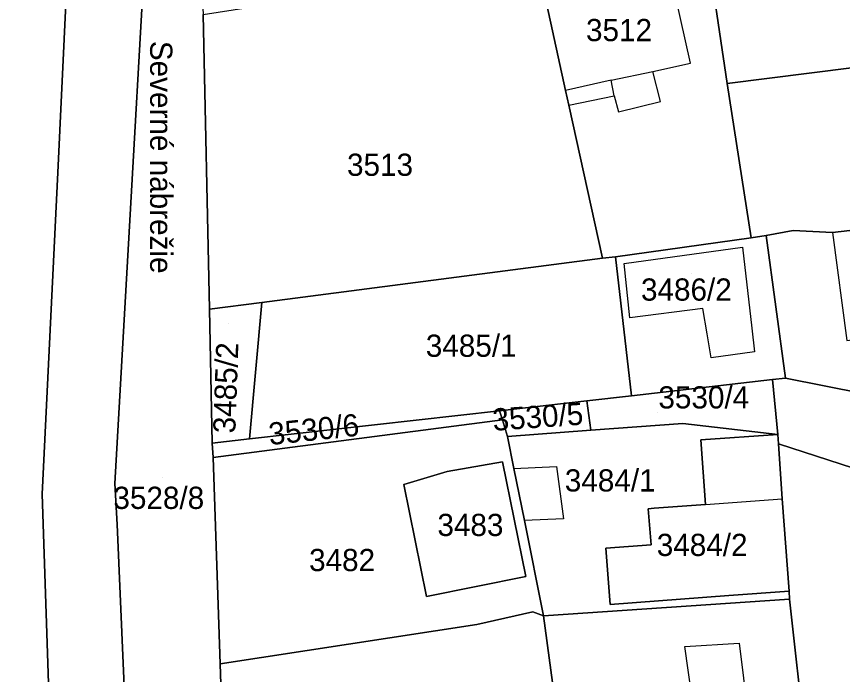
# Model space of a CAD drawing. Extents: x -262657 to -261595, y -1238015 to -1237156.
# Drawn here: x -262343.6 to -262269.2, y -1237502.5 to -1237443.2 of the extents above; entities that cross this region are included whole.
import ezdxf

# ---------------------------------------------------------------- set-up
doc = ezdxf.new("R2010")
doc.units = 0
for name, color, linetype in [('body_kn', 7, 'Continuous'), ('kladpar_druhypozemkov', 7, 'Continuous'), ('kladpar_hranice', 7, 'Continuous'), ('kladpar_parcelnecisla', 7, 'Continuous'), ('kladpar_plochy', 7, 'Continuous'), ('popisy', 7, 'Continuous'), ('zappar_hrandruhpozemk', 7, 'Continuous')]:
    doc.layers.add(name, color=color, linetype=linetype)

msp = doc.modelspace()

# ---------------------------------------------------------------- linework, layer by layer
at = {"layer": 'body_kn'}
for p, q in [((-262282.91, -1237447.41), (-262282.91, -1237447.41)), ((-262286.31, -1237448.15), (-262286.31, -1237448.15)), ((-262290.07, -1237448.94), (-262290.07, -1237448.94)), ((-262279.63, -1237449.24), (-262279.63, -1237449.24)), ((-262279.63, -1237449.24), (-262279.63, -1237449.24)), ((-262294.17, -1237449.87), (-262294.17, -1237449.87)), ((-262289.79, -1237450.34), (-262289.79, -1237450.34)), ((-262289.79, -1237450.34), (-262289.79, -1237450.34)), ((-262285.61, -1237450.85), (-262285.61, -1237450.85)), ((-262293.89, -1237451.17), (-262293.89, -1237451.17)), ((-262293.89, -1237451.17), (-262293.89, -1237451.17)), ((-262289.4, -1237451.78), (-262289.4, -1237451.78)), ((-262339.94, -1237457.24), (-262339.94, -1237457.24)), ((-262276.1, -1237462.91), (-262276.1, -1237462.91)), ((-262273.67, -1237462.47), (-262273.67, -1237462.47)), ((-262270.12, -1237462.65), (-262270.12, -1237462.65)), ((-262270.12, -1237462.65), (-262270.12, -1237462.65)), ((-262333.57, -1237463.66), (-262333.57, -1237463.66)), ((-262277.44, -1237463.14), (-262277.44, -1237463.14)), ((-262277.44, -1237463.14), (-262277.44, -1237463.14)), ((-262278.22, -1237463.98), (-262278.22, -1237463.98)), ((-262278.22, -1237463.98), (-262278.22, -1237463.98)), ((-262290.86, -1237464.97), (-262290.86, -1237464.97)), ((-262289.69, -1237464.84), (-262289.69, -1237464.84)), ((-262289.69, -1237464.84), (-262289.69, -1237464.84)), ((-262288.91, -1237465.43), (-262288.91, -1237465.43)), ((-262326.27, -1237469.57), (-262326.27, -1237469.57)), ((-262326.27, -1237469.57), (-262326.27, -1237469.57)), ((-262321.56, -1237468.96), (-262321.56, -1237468.96)), ((-262281.81, -1237469.51), (-262281.81, -1237469.51)), ((-262288.39, -1237470.34), (-262288.39, -1237470.34)), ((-262281.43, -1237471.79), (-262281.43, -1237471.79)), ((-262277.39, -1237471.27), (-262277.39, -1237471.27)), ((-262277.15, -1237473.39), (-262277.15, -1237473.39)), ((-262281.07, -1237473.95), (-262281.07, -1237473.95)), ((-262275.54, -1237475.9), (-262275.54, -1237475.9)), ((-262275.54, -1237475.9), (-262275.54, -1237475.9)), ((-262274.37, -1237475.76), (-262274.37, -1237475.76)), ((-262292.26, -1237477.81), (-262292.26, -1237477.81)), ((-262292.26, -1237477.81), (-262292.26, -1237477.81)), ((-262288.23, -1237477.35), (-262288.23, -1237477.35)), ((-262300.12, -1237478.7), (-262300.12, -1237478.7)), ((-262300.12, -1237478.7), (-262300.12, -1237478.7)), ((-262299.89, -1237478.67), (-262299.89, -1237478.67)), ((-262299.87, -1237479.53), (-262299.87, -1237479.53)), ((-262283.62, -1237479.85), (-262283.62, -1237479.85)), ((-262283.62, -1237479.85), (-262283.62, -1237479.85)), ((-262291.89, -1237480.47), (-262291.89, -1237480.47)), ((-262275.05, -1237480.84), (-262275.05, -1237480.84)), ((-262322.67, -1237481.24), (-262322.67, -1237481.24)), ((-262299.42, -1237481.04), (-262299.42, -1237481.04)), ((-262281.98, -1237481.33), (-262281.98, -1237481.33)), ((-262326.03, -1237481.62), (-262326.03, -1237481.62)), ((-262326.03, -1237481.62), (-262326.03, -1237481.62)), ((-262275, -1237481.7), (-262275, -1237481.7)), ((-262275, -1237481.7), (-262275, -1237481.7)), ((-262325.93, -1237482.92), (-262325.93, -1237482.92)), ((-262299.85, -1237483.3), (-262299.85, -1237483.3)), ((-262295, -1237483.73), (-262295, -1237483.73)), ((-262304.85, -1237484.19), (-262304.85, -1237484.19)), ((-262298.83, -1237483.91), (-262298.83, -1237483.91)), ((-262298.83, -1237483.91), (-262298.83, -1237483.91)), ((-262334.8, -1237485.25), (-262334.8, -1237485.25)), ((-262308.74, -1237485.35), (-262308.74, -1237485.35)), ((-262341.34, -1237486.23), (-262341.34, -1237486.23)), ((-262274.65, -1237486.63), (-262274.65, -1237486.63)), ((-262286.72, -1237487.53), (-262286.72, -1237487.53)), ((-262286.18, -1237487.49), (-262286.18, -1237487.49)), ((-262281.57, -1237487.15), (-262281.57, -1237487.15)), ((-262281.57, -1237487.15), (-262281.57, -1237487.15)), ((-262334.58, -1237488.96), (-262334.58, -1237488.96)), ((-262297.89, -1237488.59), (-262297.89, -1237488.59)), ((-262294.36, -1237488.44), (-262294.36, -1237488.44)), ((-262290.56, -1237491.08), (-262290.56, -1237491.08)), ((-262286.47, -1237490.77), (-262286.47, -1237490.77)), ((-262297.76, -1237493.64), (-262297.76, -1237493.64)), ((-262274.04, -1237494.95), (-262274.04, -1237494.95)), ((-262306.7, -1237495.45), (-262306.7, -1237495.45)), ((-262306.7, -1237495.45), (-262306.7, -1237495.45)), ((-262279.47, -1237495.36), (-262279.47, -1237495.36)), ((-262274, -1237495.67), (-262274, -1237495.67)), ((-262274, -1237495.67), (-262274, -1237495.67)), ((-262290.17, -1237496.17), (-262290.17, -1237496.17)), ((-262297.12, -1237496.83), (-262297.12, -1237496.83)), ((-262296.18, -1237497.18), (-262296.18, -1237497.18)), ((-262302.16, -1237497.96), (-262302.16, -1237497.96)), ((-262302.16, -1237497.96), (-262302.16, -1237497.96)), ((-262283.44, -1237499.94), (-262283.44, -1237499.94)), ((-262278.53, -1237499.64), (-262278.53, -1237499.64)), ((-262325.3, -1237501.49), (-262325.3, -1237501.49)), ((-262325.3, -1237501.49), (-262325.3, -1237501.49))]:
    msp.add_line(p, q, dxfattribs=at)
at = {"layer": 'kladpar_druhypozemkov'}
for p, q in [((-262311.05, -1237455.55), (-262311.05, -1237455.55)), ((-262282.84, -1237466.33), (-262282.84, -1237466.33)), ((-262324.59, -1237470.81), (-262324.59, -1237470.81)), ((-262301.97, -1237471.82), (-262301.97, -1237471.82)), ((-262294.83, -1237479.08), (-262294.83, -1237479.08)), ((-262285.85, -1237478.9), (-262285.85, -1237478.9)), ((-262310.39, -1237480.63), (-262310.39, -1237480.63)), ((-262330.51, -1237484.71), (-262330.51, -1237484.71)), ((-262289.93, -1237484.63), (-262289.93, -1237484.63)), ((-262302.46, -1237487.87), (-262302.46, -1237487.87)), ((-262280.41, -1237489.91), (-262280.41, -1237489.91)), ((-262313.9, -1237491.54), (-262313.9, -1237491.54))]:
    msp.add_line(p, q, dxfattribs=at)
at = {"layer": 'kladpar_hranice'}
for points in [[(-262343.65, -1237365.15), (-262343.6, -1237424.44), (-262343.15, -1237429.64), (-262338.68, -1237430.7), (-262338.79, -1237433.17), (-262339.94, -1237457.24), (-262341.34, -1237486.23), (-262339.66, -1237536.38)], [(-262326.86, -1237377.31), (-262329, -1237395.2), (-262330, -1237408.65), (-262330.77, -1237419.19), (-262331.73, -1237432.47), (-262332.03, -1237436.68), (-262333.57, -1237463.66), (-262334.8, -1237485.25), (-262334.58, -1237488.96), (-262332.58, -1237535.43), (-262332.11, -1237546.54), (-262332.06, -1237547.64), (-262339.28, -1237547.74), (-262339.33, -1237546.39), (-262339.66, -1237536.38), (-262341.34, -1237486.23), (-262339.94, -1237457.24), (-262338.79, -1237433.17), (-262338.68, -1237430.7), (-262338.44, -1237425.28), (-262337.84, -1237412.47), (-262336.73, -1237391.76)], [(-262281.57, -1237436.05), (-262262.7, -1237431.53), (-262261.1, -1237437.34), (-262258.95, -1237436.83), (-262257.9, -1237436.55), (-262256.26, -1237443.07), (-262235.03, -1237440.39), (-262237.65, -1237443.96), (-262256.96, -1237446.38), (-262279.63, -1237449.24), (-262281.57, -1237436.05)], [(-262331.73, -1237432.47), (-262327.33, -1237433.68), (-262326.82, -1237443.01), (-262326.27, -1237469.57), (-262326.03, -1237481.62), (-262325.93, -1237482.92), (-262325.3, -1237501.49), (-262324.89, -1237514.36), (-262325.13, -1237524.79), (-262325.13, -1237534.95), (-262332.58, -1237535.43), (-262334.58, -1237488.96), (-262334.8, -1237485.25), (-262333.57, -1237463.66), (-262332.03, -1237436.68), (-262331.73, -1237432.47)], [(-262289.69, -1237464.84), (-262290.86, -1237464.97), (-262293.89, -1237451.17), (-262294.17, -1237449.87), (-262296.39, -1237439.77), (-262296.71, -1237438.31), (-262291.42, -1237437.45), (-262281.57, -1237436.05), (-262279.63, -1237449.24), (-262277.44, -1237463.14), (-262289.69, -1237464.84)], [(-262326.27, -1237469.57), (-262326.82, -1237443.01), (-262296.71, -1237438.31), (-262296.39, -1237439.77), (-262294.17, -1237449.87), (-262293.89, -1237451.17), (-262290.86, -1237464.97), (-262321.56, -1237468.96), (-262326.27, -1237469.57)], [(-262279.63, -1237449.24), (-262256.96, -1237446.38), (-262237.65, -1237443.96), (-262237.36, -1237447.78), (-262242.94, -1237448.59), (-262242.2, -1237458.94), (-262254.6, -1237460.42), (-262255.2, -1237460.55), (-262259.69, -1237461.46), (-262270.12, -1237462.65), (-262273.67, -1237462.47), (-262276.1, -1237462.91), (-262277.44, -1237463.14), (-262279.63, -1237449.24)], [(-262249.82, -1237480.64), (-262274.37, -1237475.76), (-262276.1, -1237462.91), (-262273.67, -1237462.47), (-262270.12, -1237462.65), (-262259.69, -1237461.46), (-262255.2, -1237460.55), (-262254.6, -1237460.42), (-262251.24, -1237474.01), (-262249.82, -1237480.64)], [(-262277.44, -1237463.14), (-262276.1, -1237462.91), (-262274.37, -1237475.76), (-262275.54, -1237475.9), (-262288.23, -1237477.35), (-262289.69, -1237464.84), (-262277.44, -1237463.14)], [(-262289.69, -1237464.84), (-262288.23, -1237477.35), (-262292.26, -1237477.81), (-262299.89, -1237478.67), (-262300.12, -1237478.7), (-262322.67, -1237481.24), (-262321.56, -1237468.96), (-262290.86, -1237464.97), (-262289.69, -1237464.84)], [(-262326.03, -1237481.62), (-262326.27, -1237469.57), (-262321.56, -1237468.96), (-262322.67, -1237481.24), (-262326.03, -1237481.62)], [(-262275.54, -1237475.9), (-262275.05, -1237480.84), (-262283.62, -1237479.85), (-262291.89, -1237480.47), (-262292.26, -1237477.81), (-262288.23, -1237477.35), (-262275.54, -1237475.9)], [(-262253.7, -1237488.58), (-262275, -1237481.7), (-262275.05, -1237480.84), (-262275.54, -1237475.9), (-262274.37, -1237475.76), (-262249.82, -1237480.64)], [(-262292.26, -1237477.81), (-262291.89, -1237480.47), (-262299.42, -1237481.04), (-262299.87, -1237479.53), (-262300.12, -1237478.7), (-262299.89, -1237478.67), (-262292.26, -1237477.81)], [(-262300.12, -1237478.7), (-262299.87, -1237479.53), (-262325.93, -1237482.92), (-262326.03, -1237481.62), (-262322.67, -1237481.24), (-262300.12, -1237478.7)], [(-262325.3, -1237501.49), (-262325.93, -1237482.92), (-262299.87, -1237479.53), (-262299.42, -1237481.04), (-262298.83, -1237483.91), (-262297.89, -1237488.59), (-262296.18, -1237497.18)], [(-262283.62, -1237479.85), (-262275.05, -1237480.84), (-262281.98, -1237481.33), (-262281.57, -1237487.15), (-262286.18, -1237487.49), (-262286.72, -1237487.53), (-262286.47, -1237490.77), (-262290.56, -1237491.08), (-262290.17, -1237496.17), (-262279.47, -1237495.36), (-262274.04, -1237494.95), (-262274, -1237495.67), (-262296.18, -1237497.18), (-262297.89, -1237488.59), (-262298.83, -1237483.91), (-262299.42, -1237481.04), (-262291.89, -1237480.47), (-262283.62, -1237479.85)], [(-262281.57, -1237487.15), (-262281.98, -1237481.33), (-262275.05, -1237480.84), (-262275, -1237481.7), (-262274.65, -1237486.63), (-262274.04, -1237494.95), (-262279.47, -1237495.36), (-262290.17, -1237496.17), (-262290.56, -1237491.08), (-262286.47, -1237490.77), (-262286.72, -1237487.53), (-262286.18, -1237487.49), (-262281.57, -1237487.15)], [(-262275, -1237481.7), (-262253.7, -1237488.58), (-262252.4, -1237496.67), (-262250.53, -1237510.33), (-262257.99, -1237511.25), (-262257.63, -1237514.11), (-262271.94, -1237516.16), (-262272.6, -1237508.36), (-262274, -1237495.67), (-262274.04, -1237494.95), (-262274.65, -1237486.63), (-262275, -1237481.7)], [(-262297.76, -1237493.64), (-262299.85, -1237483.3), (-262304.85, -1237484.19), (-262308.74, -1237485.35), (-262306.7, -1237495.45), (-262297.76, -1237493.64)], [(-262306.7, -1237495.45), (-262308.74, -1237485.35), (-262304.85, -1237484.19), (-262299.85, -1237483.3), (-262297.76, -1237493.64), (-262306.7, -1237495.45)], [(-262274, -1237495.67), (-262272.6, -1237508.36), (-262273.09, -1237508.39), (-262277.39, -1237508.85), (-262282.06, -1237509.39), (-262284.85, -1237509.74), (-262294.34, -1237510.76), (-262296.18, -1237497.18), (-262274, -1237495.67)], [(-262296.18, -1237497.18), (-262297.12, -1237496.83), (-262302.16, -1237497.96), (-262325.3, -1237501.49)], [(-262302.16, -1237497.96), (-262297.12, -1237496.83), (-262296.18, -1237497.18), (-262294.34, -1237510.76), (-262310.72, -1237512.59), (-262317.09, -1237513.38), (-262324.89, -1237514.36), (-262325.3, -1237501.49), (-262302.16, -1237497.96)]]:
    msp.add_lwpolyline(points, dxfattribs=at)
at = {"layer": 'kladpar_plochy'}
for p, q in [((-262325.93, -1237482.92), (-262299.87, -1237479.53)), ((-262299.87, -1237479.53), (-262299.42, -1237481.04)), ((-262299.42, -1237481.04), (-262298.83, -1237483.91)), ((-262325.3, -1237501.49), (-262325.93, -1237482.92)), ((-262299.85, -1237483.3), (-262304.85, -1237484.19)), ((-262297.76, -1237493.64), (-262299.85, -1237483.3)), ((-262304.85, -1237484.19), (-262308.74, -1237485.35)), ((-262298.83, -1237483.91), (-262297.89, -1237488.59)), ((-262308.74, -1237485.35), (-262306.7, -1237495.45)), ((-262297.89, -1237488.59), (-262296.18, -1237497.18)), ((-262306.7, -1237495.45), (-262297.76, -1237493.64)), ((-262297.12, -1237496.83), (-262302.16, -1237497.96)), ((-262296.18, -1237497.18), (-262297.12, -1237496.83)), ((-262302.16, -1237497.96), (-262325.3, -1237501.49))]:
    msp.add_line(p, q, dxfattribs=at)
for points in [[(-262343.65, -1237365.15), (-262343.6, -1237424.44), (-262343.15, -1237429.64), (-262338.68, -1237430.7), (-262338.79, -1237433.17), (-262339.94, -1237457.24), (-262341.34, -1237486.23), (-262339.66, -1237536.38)], [(-262326.86, -1237377.31), (-262329, -1237395.2), (-262330, -1237408.65), (-262330.77, -1237419.19), (-262331.73, -1237432.47), (-262332.03, -1237436.68), (-262333.57, -1237463.66), (-262334.8, -1237485.25), (-262334.58, -1237488.96), (-262332.58, -1237535.43), (-262332.11, -1237546.54), (-262332.06, -1237547.64), (-262339.28, -1237547.74), (-262339.33, -1237546.39), (-262339.66, -1237536.38), (-262341.34, -1237486.23), (-262339.94, -1237457.24), (-262338.79, -1237433.17), (-262338.68, -1237430.7), (-262338.44, -1237425.28), (-262337.84, -1237412.47), (-262336.73, -1237391.76)], [(-262253.7, -1237488.58), (-262275, -1237481.7), (-262275.05, -1237480.84), (-262275.54, -1237475.9), (-262274.37, -1237475.76), (-262249.82, -1237480.64)]]:
    msp.add_lwpolyline(points, dxfattribs=at)
for points in [[(-262281.57, -1237436.05), (-262262.7, -1237431.53), (-262261.1, -1237437.34), (-262258.95, -1237436.83), (-262257.9, -1237436.55), (-262256.26, -1237443.07), (-262235.03, -1237440.39), (-262237.65, -1237443.96), (-262256.96, -1237446.38), (-262279.63, -1237449.24)], [(-262331.73, -1237432.47), (-262327.33, -1237433.68), (-262326.82, -1237443.01), (-262326.27, -1237469.57), (-262326.03, -1237481.62), (-262325.93, -1237482.92), (-262325.3, -1237501.49), (-262324.89, -1237514.36), (-262325.13, -1237524.79), (-262325.13, -1237534.95), (-262332.58, -1237535.43), (-262334.58, -1237488.96), (-262334.8, -1237485.25), (-262333.57, -1237463.66), (-262332.03, -1237436.68)], [(-262289.69, -1237464.84), (-262290.86, -1237464.97), (-262293.89, -1237451.17), (-262294.17, -1237449.87), (-262296.39, -1237439.77), (-262296.71, -1237438.31), (-262291.42, -1237437.45), (-262281.57, -1237436.05), (-262279.63, -1237449.24), (-262277.44, -1237463.14)], [(-262326.27, -1237469.57), (-262326.82, -1237443.01), (-262296.71, -1237438.31), (-262296.39, -1237439.77), (-262294.17, -1237449.87), (-262293.89, -1237451.17), (-262290.86, -1237464.97), (-262321.56, -1237468.96)], [(-262279.63, -1237449.24), (-262256.96, -1237446.38), (-262237.65, -1237443.96), (-262237.36, -1237447.78), (-262242.94, -1237448.59), (-262242.2, -1237458.94), (-262254.6, -1237460.42), (-262255.2, -1237460.55), (-262259.69, -1237461.46), (-262270.12, -1237462.65), (-262273.67, -1237462.47), (-262276.1, -1237462.91), (-262277.44, -1237463.14)], [(-262249.82, -1237480.64), (-262274.37, -1237475.76), (-262276.1, -1237462.91), (-262273.67, -1237462.47), (-262270.12, -1237462.65), (-262259.69, -1237461.46), (-262255.2, -1237460.55), (-262254.6, -1237460.42), (-262251.24, -1237474.01)], [(-262277.44, -1237463.14), (-262276.1, -1237462.91), (-262274.37, -1237475.76), (-262275.54, -1237475.9), (-262288.23, -1237477.35), (-262289.69, -1237464.84)], [(-262289.69, -1237464.84), (-262288.23, -1237477.35), (-262292.26, -1237477.81), (-262299.89, -1237478.67), (-262300.12, -1237478.7), (-262322.67, -1237481.24), (-262321.56, -1237468.96), (-262290.86, -1237464.97)], [(-262326.03, -1237481.62), (-262326.27, -1237469.57), (-262321.56, -1237468.96), (-262322.67, -1237481.24)], [(-262275.54, -1237475.9), (-262275.05, -1237480.84), (-262283.62, -1237479.85), (-262291.89, -1237480.47), (-262292.26, -1237477.81), (-262288.23, -1237477.35)], [(-262292.26, -1237477.81), (-262291.89, -1237480.47), (-262299.42, -1237481.04), (-262299.87, -1237479.53), (-262300.12, -1237478.7), (-262299.89, -1237478.67)], [(-262300.12, -1237478.7), (-262299.87, -1237479.53), (-262325.93, -1237482.92), (-262326.03, -1237481.62), (-262322.67, -1237481.24)], [(-262283.62, -1237479.85), (-262275.05, -1237480.84), (-262281.98, -1237481.33), (-262281.57, -1237487.15), (-262286.18, -1237487.49), (-262286.72, -1237487.53), (-262286.47, -1237490.77), (-262290.56, -1237491.08), (-262290.17, -1237496.17), (-262279.47, -1237495.36), (-262274.04, -1237494.95), (-262274, -1237495.67), (-262296.18, -1237497.18), (-262297.89, -1237488.59), (-262298.83, -1237483.91), (-262299.42, -1237481.04), (-262291.89, -1237480.47)], [(-262281.57, -1237487.15), (-262281.98, -1237481.33), (-262275.05, -1237480.84), (-262275, -1237481.7), (-262274.65, -1237486.63), (-262274.04, -1237494.95), (-262279.47, -1237495.36), (-262290.17, -1237496.17), (-262290.56, -1237491.08), (-262286.47, -1237490.77), (-262286.72, -1237487.53), (-262286.18, -1237487.49)], [(-262275, -1237481.7), (-262253.7, -1237488.58), (-262252.4, -1237496.67), (-262250.53, -1237510.33), (-262257.99, -1237511.25), (-262257.63, -1237514.11), (-262271.94, -1237516.16), (-262272.6, -1237508.36), (-262274, -1237495.67), (-262274.04, -1237494.95), (-262274.65, -1237486.63)], [(-262306.7, -1237495.45), (-262308.74, -1237485.35), (-262304.85, -1237484.19), (-262299.85, -1237483.3), (-262297.76, -1237493.64)], [(-262274, -1237495.67), (-262272.6, -1237508.36), (-262273.09, -1237508.39), (-262277.39, -1237508.85), (-262282.06, -1237509.39), (-262284.85, -1237509.74), (-262294.34, -1237510.76), (-262296.18, -1237497.18)], [(-262302.16, -1237497.96), (-262297.12, -1237496.83), (-262296.18, -1237497.18), (-262294.34, -1237510.76), (-262310.72, -1237512.59), (-262317.09, -1237513.38), (-262324.89, -1237514.36), (-262325.3, -1237501.49)]]:
    msp.add_lwpolyline(points, close=True, dxfattribs=at)
at = {"layer": 'zappar_hrandruhpozemk'}
for p, q in [((-262290.07, -1237448.94), (-262286.31, -1237448.15)), ((-262290.07, -1237448.94), (-262294.17, -1237449.87)), ((-262289.79, -1237450.34), (-262290.07, -1237448.94)), ((-262289.4, -1237451.78), (-262285.61, -1237450.85)), ((-262281.81, -1237469.51), (-262288.39, -1237470.34)), ((-262298.83, -1237483.91), (-262295, -1237483.73)), ((-262295, -1237483.73), (-262294.36, -1237488.44)), ((-262281.57, -1237487.15), (-262274.65, -1237486.63)), ((-262294.36, -1237488.44), (-262297.89, -1237488.59)), ((-262282.06, -1237509.39), (-262283.44, -1237499.94))]:
    msp.add_line(p, q, dxfattribs=at)
for points in [[(-262285.61, -1237450.85), (-262286.31, -1237448.15), (-262282.91, -1237447.41), (-262285.18, -1237437.31), (-262296.39, -1237439.77)], [(-262293.89, -1237451.17), (-262289.79, -1237450.34), (-262289.4, -1237451.78)], [(-262270.12, -1237462.65), (-262268.84, -1237472.37), (-262265.33, -1237471.94)], [(-262288.39, -1237470.34), (-262288.91, -1237465.43), (-262278.22, -1237463.98)], [(-262278.22, -1237463.98), (-262277.39, -1237471.27), (-262277.15, -1237473.39), (-262281.07, -1237473.95), (-262281.43, -1237471.79), (-262281.81, -1237469.51)], [(-262283.44, -1237499.94), (-262278.53, -1237499.64), (-262277.39, -1237508.85)]]:
    msp.add_lwpolyline(points, dxfattribs=at)

# ---------------------------------------------------------------- texts
at = {"layer": 'kladpar_parcelnecisla'}
for s, p in [('3512', (-262292.335, -1237445.42)), ('3513', (-262313.87, -1237457.55)), ('3486/2', (-262287.38, -1237468.79)), ('3485/1', (-262306.77, -1237473.85)), ('3530/4', (-262285.811, -1237478.5)), ('3484/1', (-262294.244, -1237485.98)), ('3528/8', (-262334.919, -1237487.55)), ('3483', (-262305.726, -1237489.99)), ('3484/2', (-262285.96, -1237491.79)), ('3482', (-262317.29, -1237493.15))]:
    msp.add_text(s, height=2, dxfattribs=at).set_placement(p)
for s, rotation, p in [('3485/2', 88, (-262323.939, -1237480.767)), ('3530/5', 4, (-262300.684, -1237480.52)), ('3530/6', 6, (-262320.829, -1237481.802))]:
    msp.add_text(s, height=2, rotation=rotation, dxfattribs=at).set_placement(p)
at = {"layer": 'popisy'}
msp.add_text('Severné nábrežie', height=2, rotation=270, dxfattribs=at).set_placement((-262331.61, -1237445.389))

doc.saveas('drawing.dxf')
